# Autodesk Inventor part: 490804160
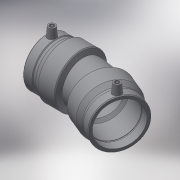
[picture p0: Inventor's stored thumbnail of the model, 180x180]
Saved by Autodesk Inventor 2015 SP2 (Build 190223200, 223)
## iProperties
Created: 2017-06
Part Number: 490804160
Material: Generic
Description: PLASSON 22.5° ELBOW 160
Document SubType Name: Modeling
Designer: KIM
Mass: 55.0731 g
Surface Area: 148.067 cm^2
Volume: 55.0731 cm^3
Density: 1 g/cm^3
Appearance: Default
Author: KIM
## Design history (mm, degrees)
derived "490804.ipt"
feature "Solid1::490804.ipt"
tag "TaggingFeature1"
body "Solid1"
other parameters: "d14" = 17.6296, "d19" = 3.52592, "d20" = 168 deg, "d22" = 192.28, "d23" = 209, "d24" = 186.5116, "d29" = 106, "d35" = 15, "d39" = 5 deg, "d45" = 4, "d46" = 14, "d47" = 0, "d67" = 45 deg, "d71" = 157.5 deg, "d75" = 10.45, "d82" = 45 deg, "d83" = 86, "d84" = 188.1, "d94" = 157.5 deg, "d95" = 93.2558, "d98" = 302, "d99" = 90.6, "d105" = 24.94, "d106" = 6.235, "L_" = 302, "L_1" = 86, "D_" = 209, "A_" = 106, "d_2" = 12
